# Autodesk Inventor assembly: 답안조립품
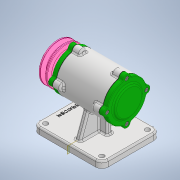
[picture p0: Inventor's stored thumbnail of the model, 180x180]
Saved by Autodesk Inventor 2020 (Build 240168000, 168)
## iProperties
Created: 2022-11
Part Number: 답안조립품
Document SubType Name: Assembly
Designer: owner
Author: owner
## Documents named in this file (12)
- C:\Users\owner\Desktop\721108V1012\답안조립품.iam
- C:\Users\owner\Desktop\721108V1012\본체.ipt
- C:\Users\owner\Desktop\721108V1012\축.ipt
- C:\Users\owner\Desktop\721108V1012\키 4 x 4.ipt
- C:\Users\owner\Desktop\721108V1012\V-벨트풀리.ipt
- C:\Users\owner\Desktop\721108V1012\개스킷.ipt
- C:\Users\owner\Desktop\721108V1012\너트 M12 x 1.25.ipt
- C:\Users\owner\Desktop\721108V1012\뒤커버.ipt
- C:\Users\owner\Desktop\721108V1012\베어링 6204.ipt
- C:\Users\owner\Desktop\721108V1012\볼트 M4 x 12.ipt
- C:\Users\owner\Desktop\721108V1012\앞커버.ipt
- C:\Users\owner\Desktop\721108V1012\오일 실.ipt
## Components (8 placed, 6 different names)
1. KS B 1311 (I) 4 x 4 x 12:1
2. V-벨트풀리:1
3. 개스킷:1
4. KS B 1012 클래스 1 일반 - 미터 M12x1.25:1
5. KS B 2023 6204 - 20 x 47 x 14:1
6. KS B 2804 D D - 20 32 8:1
7. KS B 2023 6204 - 20 x 47 x 14:2
8. 개스킷:2
